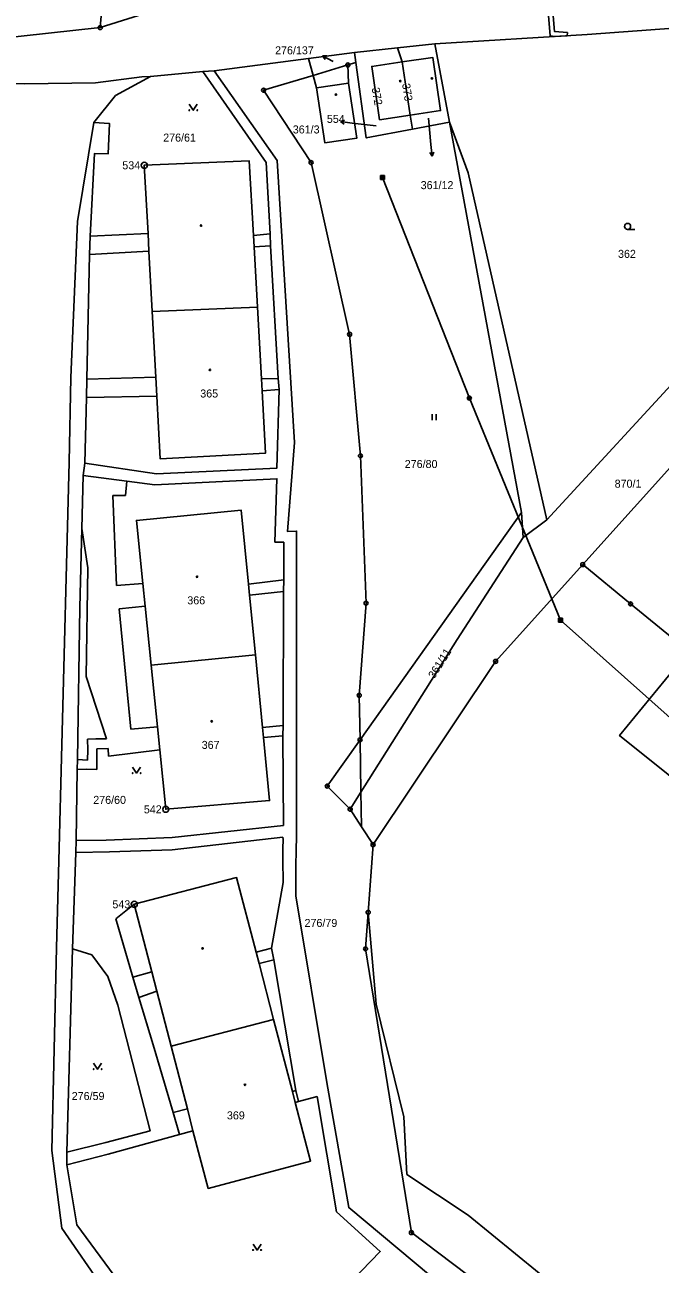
# Model space of a CAD drawing. Extents: x -745926 to -742978, y -968282 to -965689.
# Drawn here: x -744856.3 to -744776.9, y -966906.6 to -966751.7 of the extents above; entities that cross this region are included whole.
import ezdxf

# ---------------------------------------------------------------- set-up
doc = ezdxf.new("R2010")
doc.units = 0
for name, color, linetype in [('Hranice parcel', 7, 'Continuous'), ('Parcelní čísla', 7, 'Continuous'), ('Pop  PČ popisy', 7, 'Continuous'), ('Poz předměty', 7, 'Continuous'), ('Vnitřní kresba', 7, 'Continuous'), ('Věcná břemena k části', 7, 'Continuous'), ('Značky bodu BP', 7, 'Continuous'), ('Značky budov', 7, 'Continuous'), ('Značky kultur', 7, 'Continuous')]:
    doc.layers.add(name, color=color, linetype=linetype)

msp = doc.modelspace()

# ---------------------------------------------------------------- linework, layer by layer
at = {"layer": 'Hranice parcel'}
for p, q in [((-744845.2, -966732.8), (-744846.88, -966752.06)), ((-744846.88, -966752.06), (-744838.62, -966749.45)), ((-744860.98, -966753.59), (-744846.88, -966752.06)), ((-744805.06, -966754.1), (-744809.73, -966754.59)), ((-744803.23, -966763.87), (-744805.06, -966754.1)), ((-744820.86, -966755.92), (-744815.11, -966755.17)), ((-744809.73, -966754.59), (-744815.11, -966755.17)), ((-744815.11, -966755.17), (-744814.94, -966756.43)), ((-744809.15, -966756.36), (-744809.73, -966754.59)), ((-744820.86, -966755.92), (-744832.65, -966757.45)), ((-744820.28, -966758.03), (-744820.86, -966755.92)), ((-744815.94, -966756.73), (-744820.28, -966758.03)), ((-744814.94, -966756.43), (-744815.94, -966756.73)), ((-744815.94, -966756.73), (-744815.86, -966759.02)), ((-744808.16, -966763.01), (-744809.15, -966756.36)), ((-744834.06, -966757.54), (-744840.59, -966758.19)), ((-744832.65, -966757.45), (-744834.06, -966757.54)), ((-744807.85, -966764.74), (-744808.16, -966763.01)), ((-744803.23, -966763.87), (-744807.85, -966764.74)), ((-744794.26, -966812.65), (-744803.23, -966763.87)), ((-744848.79, -966806.48), (-744849.02, -966808.05)), ((-744814.42, -966841.08), (-744794.26, -966812.65)), ((-744794.03, -966815.77), (-744794.26, -966812.65)), ((-744780.62, -966824.08), (-744786.59, -966819.18)), ((-744773.37, -966830.03), (-744780.62, -966824.08)), ((-744840.52, -966831.75), (-744827.49, -966830.47)), ((-744849.89, -966853.67), (-744849.93, -966855.16)), ((-744822.12, -966886.29), (-744822.51, -966886.39))]:
    msp.add_line(p, q, dxfattribs=at)
for points in [[(-744745.02, -966744.39), (-744752.16, -966749.07), (-744766.19, -966751.48), (-744786.05, -966752.91), (-744805.06, -966754.1)], [(-744807.85, -966764.74), (-744813.65, -966765.84), (-744814.94, -966756.43)], [(-744809.15, -966756.36), (-744812.96, -966756.92), (-744811.97, -966763.57), (-744808.16, -966763.01)], [(-744808.16, -966763.01), (-744804.35, -966762.44), (-744805.34, -966755.79), (-744809.15, -966756.36)], [(-744840.59, -966758.19), (-744841.68, -966758.23), (-744847.46, -966758.96), (-744856.34, -966759.09), (-744864.98, -966758.9), (-744882.74, -966758.04)], [(-744848.79, -966806.48), (-744839.86, -966807.81), (-744824.82, -966807.13), (-744824.54, -966797.31), (-744824.65, -966795.91), (-744825.59, -966779.32), (-744825.65, -966777.85), (-744826.15, -966768.9), (-744834.06, -966757.54)], [(-744840.59, -966758.19), (-744844.99, -966760.55), (-744847.66, -966763.94), (-744845.72, -966764.06), (-744845.9, -966767.84), (-744847.61, -966767.81), (-744848.15, -966778.11), (-744848.22, -966780.43), (-744848.54, -966796), (-744848.61, -966798.27), (-744848.79, -966806.48)], [(-744627.78, -966987.01), (-744649.71, -966979.39), (-744654.61, -966977.79), (-744692.27, -966963.9), (-744738.66, -966949.62), (-744739.71, -966948.97), (-744740.38, -966948.96), (-744778.84, -966930.46), (-744815.82, -966899.53), (-744818.58, -966883.89), (-744822.45, -966860.57), (-744822.45, -966858.85), (-744822.42, -966856.77), (-744822.4, -966854.94), (-744822.37, -966853.08), (-744822.37, -966851.59), (-744822.35, -966814.99), (-744823.48, -966815.03), (-744822.59, -966803.93), (-744824.77, -966768.68), (-744832.65, -966757.45)], [(-744814.42, -966841.08), (-744814.52, -966835.52), (-744813.67, -966824), (-744814.36, -966805.58), (-744815.72, -966790.4), (-744820.54, -966768.93), (-744826.46, -966759.89), (-744820.28, -966758.03)], [(-744815.86, -966759.02), (-744814.8, -966765.86), (-744818.81, -966766.48), (-744819.86, -966759.6), (-744820.28, -966758.03)], [(-744827.23, -966787), (-744827.65, -966779.47), (-744827.73, -966778.04), (-744828.25, -966768.73), (-744841.38, -966769.27), (-744840.91, -966777.8), (-744840.79, -966780.02), (-744840.38, -966787.54), (-744839.93, -966795.77), (-744839.8, -966798.11), (-744839.38, -966805.96), (-744826.22, -966805.23), (-744826.66, -966797.46), (-744826.74, -966795.95), (-744827.23, -966787)], [(-744794.03, -966815.77), (-744791.06, -966813.58), (-744773.11, -966794.1), (-744766.35, -966786.37)], [(-744768.01, -966798.53), (-744773.76, -966804.91), (-744786.59, -966819.18)], [(-744849.02, -966808.05), (-744849.18, -966814.65), (-744849.42, -966824.52), (-744849.7, -966843.55), (-744849.76, -966844.78), (-744849.89, -966853.67)], [(-744849.89, -966853.67), (-744846.14, -966853.6), (-744837.88, -966853.3), (-744823.98, -966851.78), (-744824.06, -966840.56), (-744824.02, -966839.3), (-744823.97, -966822.52), (-744823.93, -966821.08), (-744823.94, -966816.38), (-744825.05, -966816.37), (-744824.81, -966808.44), (-744840.06, -966809.21), (-744843.55, -966808.76), (-744849.02, -966808.05)], [(-744827.49, -966830.47), (-744828.22, -966823.01), (-744828.36, -966821.6), (-744829.26, -966812.38), (-744842.35, -966813.66), (-744841.55, -966821.53), (-744841.26, -966824.35), (-744840.52, -966831.75)], [(-744815.65, -966849.75), (-744814.3, -966847.61), (-744802.26, -966828.53), (-744794.03, -966815.77)], [(-744786.59, -966819.18), (-744797.47, -966831.27), (-744812.79, -966854.17)], [(-744671.3, -966929.27), (-744781.98, -966840.55), (-744773.37, -966830.03)], [(-744840.52, -966831.75), (-744839.74, -966839.43), (-744839.45, -966842.33), (-744838.69, -966849.76), (-744825.71, -966848.66), (-744826.48, -966840.8), (-744826.6, -966839.52), (-744827.49, -966830.47)], [(-744815.65, -966849.75), (-744818.52, -966846.86), (-744814.42, -966841.08)], [(-744812.79, -966854.17), (-744814.22, -966851.96), (-744815.65, -966849.75)], [(-744822.12, -966886.29), (-744822.45, -966884.89), (-744825.19, -966868.55), (-744825.48, -966867.11), (-744824.03, -966858.92), (-744824.04, -966858.11), (-744824.07, -966856.86), (-744824.06, -966856.19), (-744824.06, -966854.99), (-744824.05, -966854.64), (-744824.03, -966853.53), (-744824.07, -966853.25), (-744837.9, -966854.82), (-744845.73, -966855.06), (-744849.93, -966855.16)], [(-744812.79, -966854.17), (-744813.4, -966862.64), (-744813.73, -966867.2), (-744808, -966902.66), (-744776.73, -966926.26), (-744745.23, -966937.12), (-744720.11, -966945.77), (-744707.11, -966950.26), (-744691.81, -966955.53), (-744673.4, -966962.06), (-744650.22, -966970.28), (-744647.24, -966971.34)], [(-744849.93, -966855.16), (-744850.35, -966867.18), (-744851.04, -966892.62), (-744851.07, -966894.18)], [(-744822.51, -966886.39), (-744822.86, -966885.03), (-744825.21, -966876.04), (-744827.04, -966869.01), (-744827.41, -966867.61), (-744829.84, -966858.3), (-744842.62, -966861.63), (-744840.42, -966870.07), (-744839.79, -966872.48), (-744838, -966879.37), (-744835.96, -966887.21), (-744835.3, -966889.94)], [(-744829.06, -966923.12), (-744822.41, -966915.9), (-744811.89, -966905.04), (-744817.34, -966900.06), (-744819.79, -966885.67), (-744822.12, -966886.29)], [(-744835.3, -966889.94), (-744833.38, -966897.14), (-744820.59, -966893.74), (-744822.51, -966886.39)], [(-744835.3, -966889.94), (-744836.97, -966890.4), (-744845.88, -966892.85), (-744851.07, -966894.18)], [(-744851.07, -966894.18), (-744849.82, -966901.7), (-744844.56, -966908.83), (-744829.06, -966923.12)]]:
    msp.add_lwpolyline(points, dxfattribs=at)
at = {"layer": 'Pop  PČ popisy'}
for p, q in [((-744817.77, -966756.28), (-744819.11, -966755.6)), ((-744819.11, -966755.6), (-744818.55, -966755.6)), ((-744819.11, -966755.6), (-744818.77, -966756.05)), ((-744805.87, -966763.38), (-744805.55, -966766.66)), ((-744816.87, -966763.81), (-744816.34, -966763.62)), ((-744815.38, -966763.99), (-744816.87, -966763.81)), ((-744816.87, -966763.81), (-744816.4, -966764.12)), ((-744812.42, -966764.33), (-744815.38, -966763.99)), ((-744805.39, -966768.15), (-744805.69, -966767.68)), ((-744805.55, -966766.66), (-744805.39, -966768.15)), ((-744805.39, -966768.15), (-744805.2, -966767.63))]:
    msp.add_line(p, q, dxfattribs=at)
at = {"layer": 'Poz předměty'}
for p, q in [((-744811.84, -966770.54), (-744811.34, -966770.54)), ((-744811.84, -966771.04), (-744811.84, -966770.54)), ((-744811.84, -966770.64), (-744811.34, -966770.64)), ((-744811.84, -966770.74), (-744811.34, -966770.74)), ((-744811.84, -966770.84), (-744811.34, -966770.84)), ((-744811.84, -966770.94), (-744811.34, -966770.94)), ((-744811.84, -966771.04), (-744811.34, -966771.04)), ((-744811.74, -966771.04), (-744811.74, -966770.54)), ((-744811.64, -966771.04), (-744811.64, -966770.54)), ((-744811.59, -966770.79), (-744800.75, -966798.37)), ((-744811.54, -966771.04), (-744811.54, -966770.54)), ((-744811.44, -966771.04), (-744811.44, -966770.54)), ((-744811.34, -966771.04), (-744811.34, -966770.54)), ((-744800.75, -966798.37), (-744789.36, -966826.11)), ((-744789.61, -966825.86), (-744789.11, -966825.86)), ((-744789.61, -966826.36), (-744789.61, -966825.86)), ((-744789.61, -966825.96), (-744789.11, -966825.96)), ((-744789.61, -966826.06), (-744789.11, -966826.06)), ((-744789.61, -966826.16), (-744789.11, -966826.16)), ((-744789.61, -966826.26), (-744789.11, -966826.26)), ((-744789.61, -966826.36), (-744789.11, -966826.36)), ((-744789.51, -966826.36), (-744789.51, -966825.86)), ((-744789.41, -966826.36), (-744789.41, -966825.86)), ((-744789.36, -966826.11), (-744754.77, -966857.01)), ((-744789.31, -966826.36), (-744789.31, -966825.86)), ((-744789.21, -966826.36), (-744789.21, -966825.86)), ((-744789.11, -966826.36), (-744789.11, -966825.86))]:
    msp.add_line(p, q, dxfattribs=at)
for radius in [0.25, 0.2, 0.15, 0.1, 0.05]:
    msp.add_circle((-744800.75, -966798.37), radius, dxfattribs=at)
at = {"layer": 'Vnitřní kresba'}
for p, q in [((-744819.86, -966759.6), (-744815.86, -966759.02)), ((-744849.72, -966776.31), (-744847.66, -966763.94)), ((-744800.9, -966770.2), (-744803.23, -966763.87)), ((-744791.06, -966813.58), (-744800.9, -966770.2)), ((-744850.57, -966795.79), (-744849.72, -966776.31)), ((-744848.15, -966778.11), (-744840.91, -966777.8)), ((-744827.73, -966778.04), (-744825.65, -966777.85)), ((-744848.22, -966780.43), (-744840.79, -966780.02)), ((-744827.65, -966779.47), (-744825.59, -966779.32)), ((-744840.38, -966787.54), (-744827.23, -966787)), ((-744850.75, -966806.39), (-744850.57, -966795.79)), ((-744848.54, -966796), (-744839.93, -966795.77)), ((-744826.74, -966795.95), (-744824.65, -966795.91)), ((-744826.66, -966797.46), (-744824.54, -966797.31)), ((-744848.61, -966798.27), (-744839.8, -966798.11)), ((-744851.72, -966843.3), (-744850.75, -966806.39)), ((-744843.73, -966810.55), (-744843.55, -966808.76)), ((-744845.29, -966810.52), (-744843.73, -966810.55)), ((-744844.86, -966821.77), (-744845.29, -966810.52)), ((-744848.43, -966819.57), (-744849.18, -966814.65)), ((-744848.64, -966833.17), (-744848.43, -966819.57)), ((-744841.55, -966821.53), (-744844.86, -966821.77)), ((-744828.36, -966821.6), (-744823.93, -966821.08)), ((-744828.22, -966823.01), (-744823.97, -966822.52)), ((-744844.52, -966824.69), (-744841.26, -966824.35)), ((-744843.05, -966839.75), (-744844.52, -966824.69)), ((-744846.08, -966840.94), (-744848.64, -966833.17)), ((-744826.6, -966839.52), (-744824.02, -966839.3)), ((-744839.74, -966839.43), (-744843.05, -966839.75)), ((-744826.48, -966840.8), (-744824.06, -966840.56)), ((-744848.48, -966843.61), (-744848.43, -966842.34)), ((-744848.45, -966841), (-744847.41, -966840.94)), ((-744848.43, -966842.34), (-744848.45, -966841)), ((-744847.41, -966840.94), (-744846.08, -966840.94)), ((-744847.32, -966843.63), (-744847.3, -966842.22)), ((-744847.3, -966842.22), (-744845.9, -966842.15)), ((-744845.9, -966842.15), (-744845.84, -966843.1)), ((-744845.84, -966843.1), (-744839.45, -966842.33)), ((-744814.3, -966847.61), (-744814.42, -966841.08)), ((-744851.99, -966854.6), (-744851.72, -966843.3)), ((-744849.7, -966843.55), (-744848.48, -966843.61)), ((-744847.3, -966844.77), (-744847.32, -966843.63)), ((-744849.76, -966844.78), (-744848.54, -966844.76)), ((-744848.54, -966844.76), (-744847.3, -966844.77)), ((-744814.26, -966849.71), (-744814.3, -966847.61)), ((-744814.22, -966851.96), (-744814.26, -966849.71)), ((-744852.35, -966867.09), (-744851.99, -966854.6)), ((-744842.62, -966861.63), (-744844.95, -966863.45)), ((-744844.95, -966863.45), (-744842.8, -966870.72)), ((-744812.39, -966874.11), (-744813.4, -966862.64)), ((-744852.94, -966892.38), (-744852.35, -966867.09)), ((-744850.35, -966867.18), (-744847.91, -966867.93)), ((-744827.41, -966867.61), (-744825.48, -966867.11)), ((-744847.91, -966867.93), (-744845.92, -966870.66)), ((-744827.04, -966869.01), (-744825.19, -966868.55)), ((-744842.8, -966870.72), (-744840.42, -966870.07)), ((-744845.92, -966870.66), (-744844.7, -966874.25)), ((-744842.8, -966870.72), (-744842.04, -966873.29)), ((-744842.04, -966873.29), (-744839.79, -966872.48)), ((-744842.04, -966873.29), (-744840.28, -966879.21)), ((-744844.7, -966874.25), (-744840.65, -966889.95)), ((-744808.93, -966888.19), (-744812.39, -966874.11)), ((-744838, -966879.37), (-744825.21, -966876.04)), ((-744837.78, -966887.67), (-744840.28, -966879.21)), ((-744822.45, -966884.89), (-744822.86, -966885.03)), ((-744837.78, -966887.67), (-744835.96, -966887.21)), ((-744836.97, -966890.4), (-744837.78, -966887.67)), ((-744808.59, -966895.39), (-744808.93, -966888.19)), ((-744840.65, -966889.95), (-744846.19, -966891.41)), ((-744846.19, -966891.41), (-744851.04, -966892.62)), ((-744851.69, -966902.1), (-744852.94, -966892.38)), ((-744800.9, -966900.5), (-744808.59, -966895.39)), ((-744789.03, -966910.15), (-744800.9, -966900.5)), ((-744846.39, -966909.77), (-744851.69, -966902.1))]:
    msp.add_line(p, q, dxfattribs=at)
at = {"layer": 'Věcná břemena k části'}
msp.add_lwpolyline([(-744791.09, -966747.99), (-744790.68, -966753.1), (-744790.03, -966753.16), (-744788.55, -966753.07), (-744788.51, -966752.69), (-744790.12, -966752.54), (-744790.49, -966748.05), (-744790.21, -966747.08), (-744789.47, -966746.9), (-744789.61, -966746.33), (-744790.69, -966746.58)], close=True, dxfattribs=at)
at = {"layer": 'Značky bodu BP'}
for centre, radius in [((-744846.88, -966752.06), 0.25), ((-744846.88, -966752.06), 0.0152), ((-744815.94, -966756.73), 0.25), ((-744815.94, -966756.73), 0.0152), ((-744826.46, -966759.89), 0.25), ((-744826.46, -966759.89), 0.0152), ((-744841.38, -966769.27), 0.375), ((-744841.38, -966769.27), 0.015), ((-744820.54, -966768.93), 0.25), ((-744820.54, -966768.93), 0.0152), ((-744815.72, -966790.4), 0.25), ((-744815.72, -966790.4), 0.0152), ((-744814.36, -966805.58), 0.25), ((-744814.36, -966805.58), 0.0152), ((-744786.59, -966819.18), 0.25), ((-744786.59, -966819.18), 0.0152), ((-744813.67, -966824), 0.25), ((-744780.62, -966824.08), 0.25), ((-744813.67, -966824), 0.0152), ((-744780.62, -966824.08), 0.0152), ((-744797.47, -966831.27), 0.25), ((-744797.47, -966831.27), 0.0152), ((-744814.52, -966835.52), 0.25), ((-744814.52, -966835.52), 0.0152), ((-744814.42, -966841.08), 0.25), ((-744814.42, -966841.08), 0.0152), ((-744818.52, -966846.86), 0.25), ((-744818.52, -966846.86), 0.0152), ((-744838.69, -966849.76), 0.375), ((-744838.69, -966849.76), 0.015), ((-744815.65, -966849.75), 0.25), ((-744815.65, -966849.75), 0.0152), ((-744812.79, -966854.17), 0.25), ((-744812.79, -966854.17), 0.0152), ((-744842.62, -966861.63), 0.375), ((-744842.62, -966861.63), 0.015), ((-744813.4, -966862.64), 0.25), ((-744813.4, -966862.64), 0.0152), ((-744813.73, -966867.2), 0.25), ((-744813.73, -966867.2), 0.0152), ((-744808, -966902.66), 0.25), ((-744808, -966902.66), 0.0152)]:
    msp.add_circle(centre, radius, dxfattribs=at)
at = {"layer": 'Značky budov'}
for centre in [(-744809.39, -966758.74), (-744805.44, -966758.41), (-744817.43, -966760.43), (-744834.27, -966776.81), (-744833.17, -966794.84), (-744834.77, -966820.69), (-744832.95, -966838.76), (-744834.09, -966867.15), (-744828.79, -966884.19)]:
    msp.add_circle(centre, 0.0875, dxfattribs=at)
at = {"layer": 'Značky kultur'}
for p, q in [((-744780.98, -966777.29), (-744780.1, -966777.29)), ((-744805.41, -966801.12), (-744805.41, -966800.37)), ((-744804.91, -966801.12), (-744804.91, -966800.37))]:
    msp.add_line(p, q, dxfattribs=at)
for points in [[(-744835.75, -966761.64), (-744835.25, -966762.39), (-744834.75, -966761.64)], [(-744842.83, -966844.49), (-744842.33, -966845.24), (-744841.83, -966844.49)], [(-744847.7, -966881.49), (-744847.2, -966882.24), (-744846.7, -966881.49)], [(-744827.78, -966904.09), (-744827.28, -966904.84), (-744826.78, -966904.09)]]:
    msp.add_lwpolyline(points, dxfattribs=at)
for centre, radius in [((-744835.75, -966762.39), 0.05), ((-744834.75, -966762.39), 0.05), ((-744780.98, -966776.91), 0.375), ((-744842.83, -966845.24), 0.05), ((-744841.83, -966845.24), 0.05), ((-744847.7, -966882.24), 0.05), ((-744846.7, -966882.24), 0.05), ((-744827.78, -966904.84), 0.05), ((-744826.78, -966904.84), 0.05)]:
    msp.add_circle(centre, radius, dxfattribs=at)

# ---------------------------------------------------------------- texts
at = {"layer": 'Parcelní čísla'}
for s, p in [('276/137', (-744825.03, -966755.4)), ('554', (-744818.56, -966763.97)), ('361/3', (-744822.82, -966765.29)), ('276/61', (-744839.01, -966766.31)), ('361/12', (-744806.84, -966772.25)), ('362', (-744782.18, -966780.84)), ('365', (-744834.38, -966798.29)), ('276/80', (-744808.83, -966807.1)), ('870/1', (-744782.6, -966809.56)), ('366', (-744836, -966824.14)), ('367', (-744834.2, -966842.21)), ('276/60', (-744847.75, -966849.08)), ('276/79', (-744821.35, -966864.46)), ('276/59', (-744850.44, -966886.09)), ('369', (-744831.05, -966888.51))]:
    msp.add_text(s, height=1, dxfattribs=at).set_placement(p)
for s, rotation, p in [('372', 280, (-744812.97, -966759.64)), ('373', 279, (-744809.17, -966759.11)), ('361/11', 58, (-744805.13, -966833.51))]:
    msp.add_text(s, height=1, rotation=rotation, dxfattribs=at).set_placement(p)
at = {"layer": 'Značky bodu BP'}
for s, p in [('534', (-744844.12, -966769.77)), ('542', (-744841.43, -966850.26)), ('543', (-744845.36, -966862.13))]:
    msp.add_text(s, height=1, dxfattribs=at).set_placement(p)

doc.saveas('drawing.dxf')
